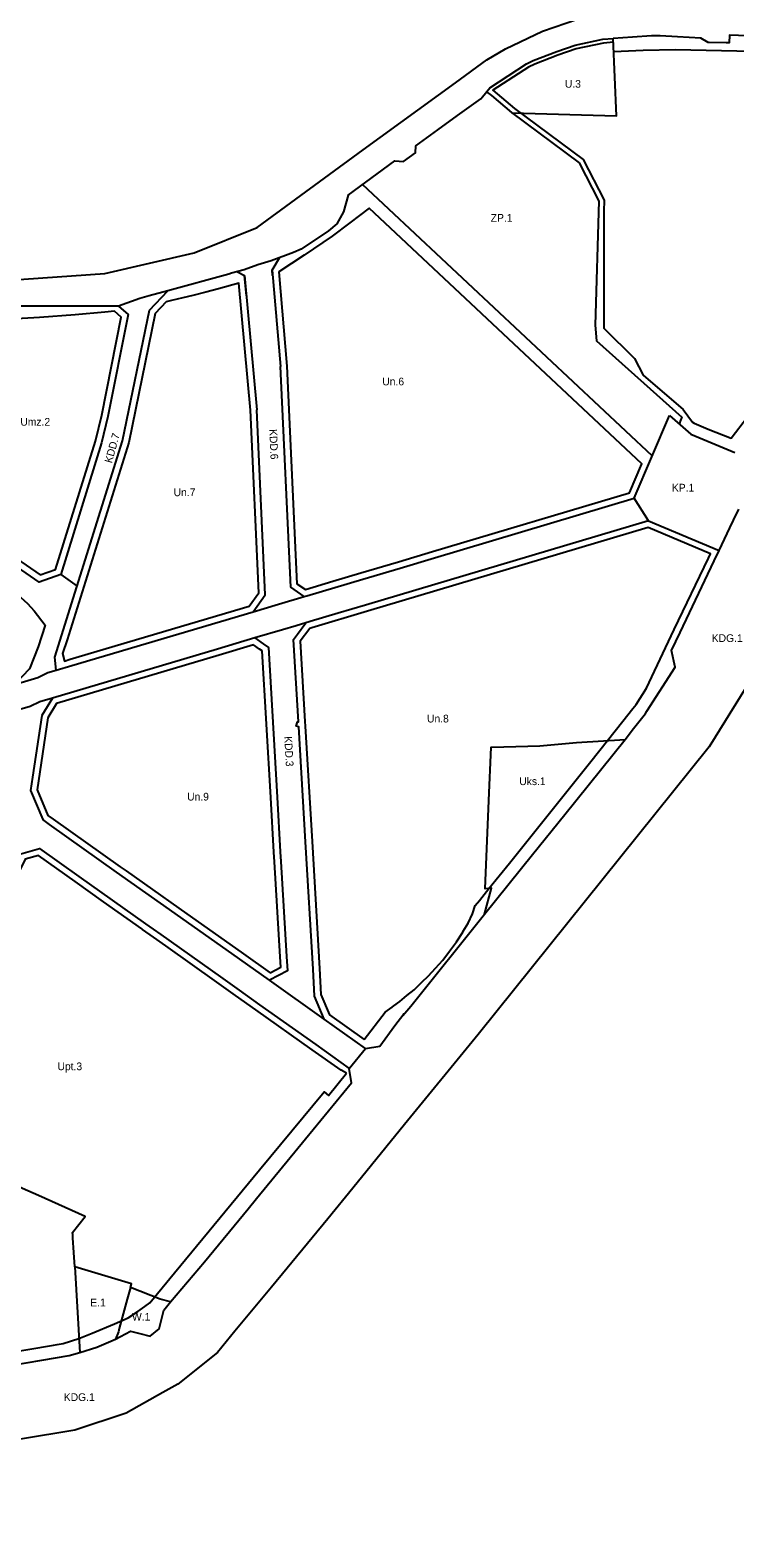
# Model space of a CAD drawing. Extents: x 7420092 to 7422347, y 5542930 to 5544880.
# Drawn here: x 7420746 to 7421294, y 5542930 to 5544105 of the extents above; entities that cross this region are included whole.
import ezdxf

# ---------------------------------------------------------------- set-up
doc = ezdxf.new("R2010")
doc.units = 0
for name, color, linetype in [('LIN_Granica Planu', 7, 'Continuous'), ('LIN_linie_rozgraniczajace', 7, 'Continuous'), ('LIN_linie_zabudowy_nieprzekraczalne', 7, 'Continuous'), ('LIN_linie_zabudowy_obowiazujace', 7, 'Continuous'), ('TXT_oznaczenia_przeznaczen', 7, 'Continuous')]:
    doc.layers.add(name, color=color, linetype=linetype)

msp = doc.modelspace()

# ---------------------------------------------------------------- linework, layer by layer
at = {"layer": 'LIN_Granica Planu'}
for points in [[(7420703.4, 5543908.1), (7420803.9, 5543915), (7420873.4, 5543931.2), (7420922.3, 5543950.9), (7421004.9, 5544011.4), (7421076.7, 5544063.6), (7421101.2, 5544081.4), (7421115.8, 5544090.1), (7421144.5, 5544103.8), (7421171.7, 5544113.2)], [(7421302.9, 5543592.8), (7421274.3, 5543546.2), (7421094.4, 5543322.2), (7421037.1, 5543252), (7420996.9, 5543202.6), (7420977.3, 5543178.6), (7420933.5, 5543125.4), (7420905.1, 5543091.2), (7420891.6, 5543074.5), (7420860.6, 5543049.8), (7420848.9, 5543043.4), (7420820.5, 5543027.2), (7420780.4, 5543014), (7420531.3, 5542972.7)]]:
    msp.add_lwpolyline(points, dxfattribs=at)
at = {"layer": 'LIN_linie_rozgraniczajace'}
for p, q in [((7420934.1, 5543917.6), (7420939.9, 5543927.3)), ((7420934.4, 5543913.5), (7420934.1, 5543917.6)), ((7420907, 5543916.4), (7420912.6, 5543913.4)), ((7420914, 5543897.7), (7420912.6, 5543913.4)), ((7421215.9, 5543740.1), (7421243.2, 5543804.5)), ((7421243.2, 5543804.5), (7421260, 5543790)), ((7421260, 5543790), (7421294.2, 5543775.5)), ((7421227, 5543722.5), (7421215.9, 5543740.1)), ((7421227, 5543722.5), (7421281.9, 5543699.2)), ((7420769.5, 5543680.5), (7420782.2, 5543671.6))]:
    msp.add_line(p, q, dxfattribs=at)
for points in [[(7420158.3, 5543240.3), (7420133.1, 5543388.4), (7420131.9, 5543396), (7420112.3, 5543390.1), (7420147.7, 5543606.6), (7420196.2, 5543606.9), (7420215.3, 5543734.8), (7420281.2, 5543725.5), (7420281.9, 5543731.7), (7420304.4, 5543913), (7420382.6, 5543894.4), (7420448.5, 5543883.7), (7420541.9, 5543881.8), (7420609.9, 5543892.9), (7420703.4, 5543908.1), (7420803.9, 5543915), (7420873.4, 5543931.2), (7420922.3, 5543950.9), (7421004.9, 5544011.4), (7421076.7, 5544063.6), (7421101.2, 5544081.4), (7421115.8, 5544090.1), (7421144.5, 5544103.8), (7421171.7, 5544113.2)], [(7421097.8, 5544052.8), (7421103.5, 5544059.8), (7421132.1, 5544078.4), (7421137.2, 5544080.9), (7421155.5, 5544088), (7421169.9, 5544092.9), (7421191.5, 5544097.5), (7421199.5, 5544098.1)], [(7421120.5, 5544040.3), (7421202.1, 5544038), (7421200.8, 5544067.9), (7421199.5, 5544098.1)], [(7421399.1, 5544096.8), (7421383.9, 5544097.8), (7421345.2, 5544098.7), (7421289.9, 5544100.6), (7421289.7, 5544094.8), (7421287.4, 5544094.8), (7421274.2, 5544094.9), (7421273.4, 5544094.9), (7421267.8, 5544098.5), (7421249.6, 5544099.4), (7421236, 5544100.1), (7421229.2, 5544100.3), (7421214.6, 5544099.2), (7421199.5, 5544098.1)], [(7420993.1, 5543976.1), (7421029.6, 5544002.7), (7421036.2, 5544002.2), (7421045.5, 5544009), (7421046, 5544014.5), (7421062.9, 5544026.9), (7421078.3, 5544038.1), (7421096.4, 5544051.2), (7421097.8, 5544052.8)], [(7421101, 5544056.7), (7421104.7, 5544053.6)], [(7421104.7, 5544053.6), (7421120.3, 5544040.4), (7421172.9, 5544001.2)], [(7421172.9, 5544001.2), (7421188.2, 5543971.5), (7421185.4, 5543874.7), (7421186.5, 5543862.6), (7421252.8, 5543803.1), (7421251.7, 5543800), (7421251, 5543797.8)], [(7420993.1, 5543976.1), (7420989.6, 5543963.2), (7420984.5, 5543953.7), (7420977.9, 5543948.2), (7420956.7, 5543933.9), (7420950.7, 5543931.5), (7420933.4, 5543924.9), (7420923, 5543921.7), (7420912.2, 5543917.8)], [(7421229.9, 5543773), (7421004.5, 5543984.4)], [(7420912.2, 5543917.8), (7420902.5, 5543915.2), (7420900.3, 5543914.5), (7420852.8, 5543901.6), (7420838.4, 5543897.7), (7420831.2, 5543895.5), (7420814.4, 5543889.6), (7420722.4, 5543889.5), (7420677.8, 5543881.8), (7420628.1, 5543873.1), (7420621.1, 5543870.6), (7420594.7, 5543862.3), (7420582.5, 5543859), (7420531.3, 5543859.9), (7420511.3, 5543860.2)], [(7420934.1, 5543917.6), (7420940.6, 5543842.5)], [(7420912.6, 5543913.4), (7420922.1, 5543808.9)], [(7420765.9, 5543606), (7420764.9, 5543616.2), (7420817.6, 5543784.7), (7420838.5, 5543886.4), (7420852.8, 5543901.6)], [(7420814.4, 5543889.6), (7420822, 5543883), (7420806.3, 5543803.6), (7420801.3, 5543783.2), (7420769.5, 5543680.5), (7420752.7, 5543674.7), (7420732.4, 5543688.7), (7420722.8, 5543694.9), (7420712.8, 5543700.3), (7420702.4, 5543705), (7420691.7, 5543708.9), (7420680.8, 5543712), (7420669.6, 5543714.3), (7420658.1, 5543727.9), (7420662.5, 5543864.5), (7420677.8, 5543881.8)], [(7420959, 5543663.4), (7420948.5, 5543670.7), (7420940.6, 5543842.5)], [(7420919.2, 5543651.6), (7420928.7, 5543664.7), (7420922.1, 5543808.9)], [(7420671.4, 5543577.4), (7420733.5, 5543594.8), (7420751.7, 5543600.4), (7420759.5, 5543604.1), (7420765.9, 5543606), (7420778.2, 5543609.7), (7420919.2, 5543651.6), (7420939.1, 5543657.5), (7420959, 5543663.4), (7420961.1, 5543664), (7420982.8, 5543670.5), (7421004.6, 5543677), (7421033.7, 5543685.6), (7421060.3, 5543693.6), (7421215.9, 5543740.1)], [(7421281.9, 5543699.2), (7421288.2, 5543712.6), (7421290.2, 5543716.9), (7421293.2, 5543723), (7421297.2, 5543731.5)], [(7421227, 5543722.5), (7421006.8, 5543656.8), (7420985.4, 5543650.4), (7420963.6, 5543643.9), (7420952.8, 5543640.7), (7420942.1, 5543637.5), (7420920.5, 5543631.2), (7420891.4, 5543622.5), (7420763, 5543584.2), (7420753.3, 5543581.3), (7420745.6, 5543577.8), (7420732.2, 5543573.8), (7420677.8, 5543557.5)], [(7420669.1, 5543699.1), (7420689.7, 5543693.5), (7420709.5, 5543684.5), (7420727.6, 5543672.6), (7420743.7, 5543658), (7420748.8, 5543652.3), (7420757.3, 5543641.1), (7420751.9, 5543624.2), (7420745.1, 5543607.1), (7420733.5, 5543594.8)], [(7420721, 5543062.8), (7420776.1, 5543072.2), (7420784.3, 5543074.4), (7420797.6, 5543078.7), (7420812.1, 5543084.8), (7420823.9, 5543091), (7420831.2, 5543089.2), (7420839.2, 5543087.3), (7420846, 5543092.9), (7420847.4, 5543098.1), (7420849.8, 5543107.4), (7420855, 5543113.9), (7420881.5, 5543145.2), (7420915.4, 5543186.5), (7420921.9, 5543194.4), (7420960.1, 5543241), (7420995.9, 5543284.6), (7420994, 5543295.8), (7421006.6, 5543311.4), (7421017.8, 5543313.2), (7421029.6, 5543329.1), (7421036.5, 5543338.4), (7421035.9, 5543336.9), (7421041.9, 5543344.4), (7421099.4, 5543415.9), (7421136.8, 5543462.4), (7421161.9, 5543493.7), (7421208.7, 5543552), (7421208.7, 5543552), (7421215.3, 5543560.5), (7421224.6, 5543572.3), (7421225.7, 5543574), (7421247.7, 5543608.5), (7421244.8, 5543621.3), (7421251.5, 5543635.5), (7421278.1, 5543691.3), (7421281.9, 5543699.2)], [(7420974.6, 5543334.2), (7420967.1, 5543352.2), (7420965.9, 5543373.2), (7420960.1, 5543472.3), (7420954.8, 5543562), (7420952.8, 5543562.5), (7420953.7, 5543565.9), (7420954.6, 5543565.7), (7420950.8, 5543630), (7420953.7, 5543634), (7420960.3, 5543642.9)], [(7420920.5, 5543631.2), (7420927.1, 5543626.5), (7420931.1, 5543623.7), (7420938, 5543507.1), (7420940.4, 5543464.6), (7420940.9, 5543457.1), (7420945.2, 5543383), (7420945.9, 5543371.7), (7420932, 5543364.5)], [(7421302.9, 5543592.8), (7421274.3, 5543546.2), (7421094.4, 5543322.2), (7421037.1, 5543252), (7420996.9, 5543202.6), (7420977.3, 5543178.6), (7420933.5, 5543125.4), (7420905.1, 5543091.2), (7420891.6, 5543074.5), (7420860.6, 5543049.8), (7420848.9, 5543043.4), (7420820.5, 5543027.2), (7420780.4, 5543014), (7420531.3, 5542972.7), (7420452.9, 5542955), (7420424.4, 5542944.7), (7420387.2, 5542930.1), (7420366.1, 5542955.3), (7420377.7, 5542960.6), (7420373.9, 5542990.6), (7420318, 5543044.4)], [(7420763, 5543584.2), (7420754.7, 5543570.7), (7420747.6, 5543522.6)], [(7421099.4, 5543415.9), (7421104.8, 5543436.1), (7421099.9, 5543435.6), (7421102.8, 5543504.6), (7421104.5, 5543546), (7421114.3, 5543546.4), (7421142.5, 5543547.2), (7421170.9, 5543549.7), (7421208.7, 5543552)], [(7420747.6, 5543522.6), (7420746.1, 5543512.2), (7420755.5, 5543489.7)], [(7421006.6, 5543311.4), (7420974.6, 5543334.2), (7420932, 5543364.5), (7420908.8, 5543381), (7420858.6, 5543416.5), (7420813, 5543448.8), (7420760.7, 5543485.8), (7420755.5, 5543489.7)], [(7420738.4, 5543463), (7420753, 5543467), (7420783.6, 5543445.4), (7420835.5, 5543408.5), (7420847.3, 5543400.2), (7420893.8, 5543367.2), (7420901.2, 5543361.9), (7420908.5, 5543356.7), (7420924.3, 5543345.4), (7420968.1, 5543314.3), (7420994, 5543295.8)], [(7420780.4, 5543141.3), (7420779.7, 5543152.5), (7420779, 5543163.8), (7420778.9, 5543166.9), (7420778.8, 5543167.4), (7420778.8, 5543167.9), (7420788.6, 5543180.5), (7420752.1, 5543196.8), (7420729, 5543207), (7420706, 5543217.3), (7420697, 5543221.3), (7420683.7, 5543227.3), (7420651.8, 5543241.5), (7420619.9, 5543255.8), (7420607.9, 5543261.1), (7420591.8, 5543268.4), (7420575.7, 5543275.7)], [(7420855, 5543113.9), (7420846.9, 5543115.9), (7420823.7, 5543125.1), (7420824.5, 5543128), (7420780.4, 5543141.3), (7420784.3, 5543074.4)], [(7420823.7, 5543125.1), (7420821.3, 5543116.1), (7420815.1, 5543093.2), (7420814.5, 5543090.7), (7420812.1, 5543084.8)]]:
    msp.add_lwpolyline(points, dxfattribs=at)
at = {"layer": 'LIN_linie_zabudowy_nieprzekraczalne'}
for points in [[(7421199.8, 5544095.2), (7421191.9, 5544094.5), (7421170.7, 5544090.1), (7421156.5, 5544085.1), (7421138.4, 5544078.2), (7421133.6, 5544075.8), (7421105.9, 5544057.8), (7421122.8, 5544043.6), (7421176, 5544003.8), (7421192.4, 5543972.2)], [(7421414, 5543952.2), (7421472.2, 5544039.3), (7421493.4, 5544067.5), (7421485.7, 5544072.1), (7421479, 5544075.3), (7421467.6, 5544079.2), (7421461, 5544080.8), (7421422.7, 5544084.4), (7421408, 5544085.5), (7421402.6, 5544085.8), (7421397.2, 5544086), (7421393.1, 5544086.1), (7421391, 5544086.2), (7421248.1, 5544089.2), (7421222.7, 5544088.8), (7421200, 5544087.7)], [(7421126.4, 5543856.3), (7421009.5, 5543966), (7420994.6, 5543954.6), (7420980.9, 5543944.2), (7420959, 5543929.4), (7420939.2, 5543916.4), (7420945.6, 5543842.8), (7420953.4, 5543673.4), (7420959.9, 5543668.8)], [(7420916.2, 5543655.9), (7420923.6, 5543666.2), (7420917.1, 5543808.6), (7420908.1, 5543907.6), (7420892.4, 5543903.2), (7420882.4, 5543900.4), (7420872.3, 5543897.9), (7420864.6, 5543896.1), (7420855.8, 5543894), (7420851.5, 5543892.9), (7420843.1, 5543884), (7420822.5, 5543783.4), (7420774.4, 5543629.7)], [(7420811.3, 5543885.7), (7420803.8, 5543884.8), (7420780.7, 5543882.9), (7420753.1, 5543880.9), (7420739.6, 5543879.9), (7420730.1, 5543879), (7420719.5, 5543877.8), (7420707.2, 5543876.3), (7420675.2, 5543871.3), (7420667.4, 5543862.6), (7420663.2, 5543729.7), (7420672.3, 5543718.9), (7420682, 5543716.9), (7420693.3, 5543713.7), (7420704.3, 5543709.6), (7420715, 5543704.8), (7420725.4, 5543699.2), (7420735.2, 5543692.9), (7420753.5, 5543680.3), (7420765.5, 5543684.4), (7420796.5, 5543784.5), (7420801.4, 5543804.6), (7420816.6, 5543881.1), (7420811.3, 5543885.7)], [(7420963.3, 5543638.6), (7420955.9, 5543628.5), (7420959.6, 5543566), (7420959.8, 5543562.3), (7420965.1, 5543472.6), (7420970.9, 5543373.5), (7420972, 5543353.3), (7420978.6, 5543337.5), (7421005.6, 5543318.2)], [(7420820.4, 5543449.7), (7420861.5, 5543420.6), (7420911.7, 5543385.1), (7420932.5, 5543370.3), (7420940.7, 5543374.6), (7420940.2, 5543382.7), (7420935.9, 5543456.8), (7420935.4, 5543464.3), (7420933, 5543506.8), (7420926.2, 5543621), (7420924.3, 5543622.4), (7420919.6, 5543625.7)], [(7421102.8, 5543435.9), (7421118.8, 5543455.8), (7421182.1, 5543535), (7421195, 5543551.2)], [(7420991.9, 5543292.1), (7420987.9, 5543294.4), (7420965.2, 5543310.2), (7420921.4, 5543341.4), (7420905.6, 5543352.6), (7420898.3, 5543357.8), (7420890.9, 5543363.1), (7420851.3, 5543391.2), (7420841.7, 5543398.1), (7420833.1, 5543404.1), (7420832.6, 5543404.4), (7420802.7, 5543425.6)]]:
    msp.add_lwpolyline(points, dxfattribs=at)
at = {"layer": 'LIN_linie_zabudowy_obowiazujace'}
for points in [[(7421192.4, 5543972.2), (7421192.3, 5543963.4), (7421192.2, 5543939.4), (7421192.3, 5543872.5), (7421216, 5543848.8), (7421222.8, 5543835.8), (7421253.9, 5543809), (7421261.2, 5543799.2), (7421262.5, 5543798.4), (7421273.4, 5543793.8), (7421291.2, 5543786.7), (7421303.9, 5543803.5), (7421310.8, 5543812.3), (7421335.7, 5543844.2), (7421362.1, 5543880), (7421371, 5543891.9), (7421396.5, 5543925.9), (7421414, 5543952.2)], [(7420959.9, 5543668.8), (7420981.4, 5543675.3), (7421003.2, 5543681.8), (7421032.3, 5543690.4), (7421058.9, 5543698.4), (7421212.2, 5543744.2), (7421221.8, 5543766.9), (7421126.4, 5543856.3)], [(7421195, 5543551.2), (7421207.1, 5543566.3), (7421214.9, 5543576.2), (7421217.3, 5543579.3), (7421225.4, 5543592.1), (7421240.3, 5543623.5), (7421247, 5543637.6), (7421273.6, 5543693.4), (7421275.1, 5543696.7), (7421226.7, 5543717.2), (7421008.2, 5543652), (7420965, 5543639.1), (7420963.3, 5543638.6)], [(7420774.4, 5543629.7), (7420771, 5543618.9), (7420772.4, 5543613.1), (7420776.8, 5543614.5), (7420916.2, 5543655.9)], [(7420919.6, 5543625.7), (7420892.9, 5543617.7), (7420766.3, 5543580), (7420759.5, 5543568.9), (7420751.2, 5543512.9), (7420759.6, 5543492.9), (7420763.6, 5543489.9), (7420815.8, 5543452.9), (7420820.4, 5543449.7)], [(7420802.7, 5543425.6), (7420780.7, 5543441.3), (7420752.1, 5543461.6), (7420741.9, 5543458.7), (7420730.6, 5543435.9), (7420716.6, 5543418.8), (7420699.9, 5543404.8), (7420656.6, 5543368.8), (7420645.8, 5543359.8), (7420639.4, 5543353.7), (7420634.1, 5543347.4), (7420629.4, 5543342.3), (7420622.3, 5543334.5), (7420600.9, 5543304.9), (7420590.9, 5543290.8), (7420579.4, 5543274)], [(7421005.6, 5543318.2), (7421022, 5543339.7), (7421027.4, 5543343.4), (7421027.8, 5543343.7), (7421031.6, 5543346.6), (7421033.4, 5543347.9), (7421038.9, 5543352.5), (7421044.6, 5543357), (7421050.6, 5543362.9), (7421055.7, 5543368), (7421061.2, 5543373.9), (7421066.8, 5543380.1), (7421072.1, 5543387), (7421077.5, 5543394.4), (7421082.5, 5543402), (7421082.8, 5543402.8), (7421086.7, 5543409), (7421089.9, 5543416.2), (7421092, 5543422.7), (7421095.4, 5543426.6), (7421102.8, 5543435.9)], [(7420614.5, 5543055.3), (7420665.4, 5543063.7), (7420763.9, 5543080.1), (7420766.7, 5543080.6), (7420771.3, 5543081.5), (7420783.7, 5543085.3), (7420793.9, 5543089.6), (7420811.3, 5543096.9), (7420822.1, 5543101.5), (7420829.5, 5543106.3), (7420835, 5543110.2), (7420838.9, 5543113.2), (7420858.1, 5543136.6), (7420924.3, 5543216.7), (7420974.5, 5543277.5), (7420977.8, 5543274.8), (7420991.9, 5543292.1)]]:
    msp.add_lwpolyline(points, dxfattribs=at)

# ---------------------------------------------------------------- texts
at = {"layer": 'TXT_oznaczenia_przeznaczen'}
for s, p in [('U.3', (7421161.9, 5544059.8)), ('ZP.1', (7421104.2, 5543955.4)), ('Un.6', (7421019.8, 5543827.9)), ('Umz.2', (7420738.1, 5543796.5)), ('Un.7', (7420857.4, 5543741.6)), ('KP.1', (7421245.2, 5543745.2)), ('Un.8', (7421054.6, 5543565.3)), ('Uks.1', (7421126.4, 5543516.5)), ('Un.9', (7420867.9, 5543504.5)), ('Upt.3', (7420767, 5543294.4)), ('E.1', (7420792.5, 5543110.4)), ('W.1', (7420825, 5543099.3))]:
    msp.add_text(s, height=6, dxfattribs=at).set_placement(p)
for s, rotation, p in [('KDD.7', 74.4857, (7420809.3, 5543766.9)), ('KDD.6', 272.5232, (7420931.8, 5543793.7)), ('KDG.1', 360, (7421276.2, 5543628)), ('KDD.3', 273.1266, (7420943.5, 5543554.4)), ('KDG.1', 360, (7420771.9, 5543036.7))]:
    msp.add_text(s, height=6, rotation=rotation, dxfattribs=at).set_placement(p)

doc.saveas('drawing.dxf')
